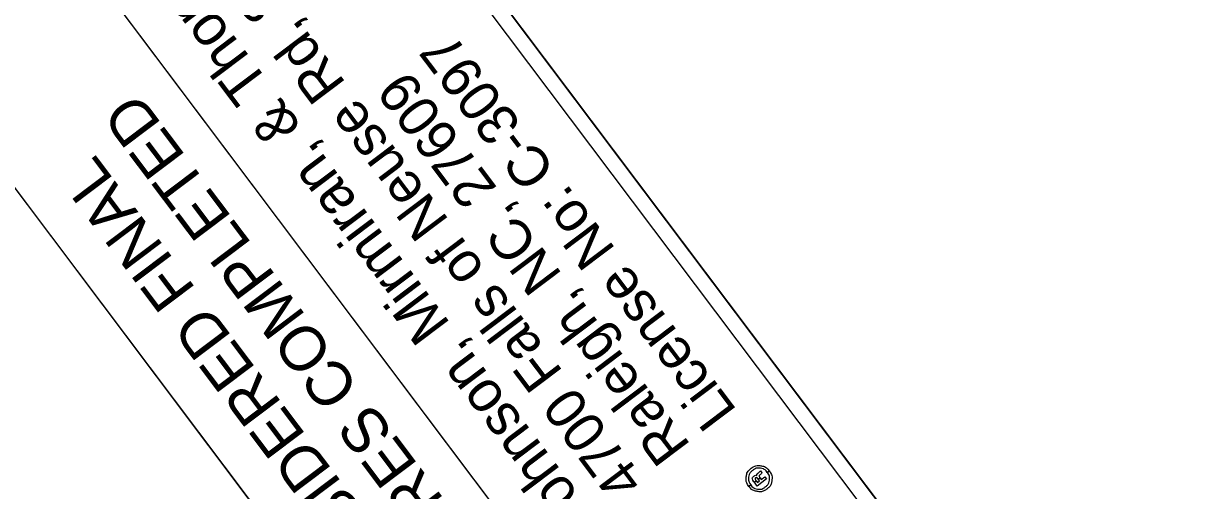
# Model space of a CAD drawing. Extents: x 1262749 to 1264921, y 774795 to 776798.
# Drawn here: x 1263207.9 to 1263352.6, y 776158.6 to 776215.8 of the extents above; entities that cross this region are included whole.
import ezdxf

# ---------------------------------------------------------------- set-up
doc = ezdxf.new("R2010")
doc.units = 0
for name, color, linetype in [('Default', 7, 'Continuous'), ('Sheet Border Standard 30in CELL', 7, 'Continuous'), ('Sheet Data Field CELL', 7, 'Continuous'), ('Sheet Layout Plan Border', 7, 'Continuous'), ('Sheet Plan Layout CELL', 7, 'Continuous')]:
    doc.layers.add(name, color=color, linetype=linetype)

msp = doc.modelspace()

# ---------------------------------------------------------------- linework, layer by layer
at = {"layer": 'Default'}
for p, q in [((1263200.09, 776243.7), (1263320.41, 776083.96)), ((1263301.64, 776069.83), (1263181.33, 776229.56))]:
    msp.add_line(p, q, dxfattribs=at)
at = {"layer": 'Sheet Border Standard 30in CELL'}
msp.add_lwpolyline([(1263151.63, 776082.06), (1263091.48, 776161.91), (1263181.32, 776229.57), (1263241.46, 776149.72)], close=True, dxfattribs=at)
at = {"layer": 'Sheet Data Field CELL'}
for p, q in [((1263298.46, 776159.92), (1263298.91, 776160.26)), ((1263298.91, 776160.26), (1263299.1, 776160)), ((1263299.2, 776160.8), (1263299.19, 776160.81)), ((1263299.2, 776160.8), (1263299.45, 776160.99)), ((1263299.45, 776160.99), (1263299.2, 776160.8)), ((1263299.44, 776161), (1263299.45, 776160.99)), ((1263296.93, 776159.09), (1263297.17, 776159.27)), ((1263297.17, 776159.27), (1263296.93, 776159.09)), ((1263297.61, 776159.6), (1263297.55, 776159.67)), ((1263297.61, 776159.6), (1263297.83, 776159.77)), ((1263297.83, 776159.77), (1263297.61, 776159.6)), ((1263297.96, 776159.14), (1263297.61, 776159.6)), ((1263297.8, 776159.8), (1263297.83, 776159.77)), ((1263297.83, 776159.77), (1263297.98, 776159.56)), ((1263299.1, 776160), (1263297.96, 776159.14)), ((1263297.98, 776159.56), (1263298.25, 776159.76)), ((1263298.1, 776159.97), (1263298.09, 776159.98)), ((1263298.1, 776159.97), (1263298.3, 776160.13)), ((1263298.3, 776160.13), (1263298.1, 776159.97)), ((1263298.25, 776159.76), (1263298.1, 776159.97)), ((1263298.3, 776160.14), (1263298.3, 776160.13)), ((1263298.3, 776160.13), (1263298.46, 776159.92))]:
    msp.add_line(p, q, dxfattribs=at)
msp.add_lwpolyline([(1263349.24, 776105.68), (1263228.9, 776265.45), (1263200.06, 776243.74), (1263320.41, 776083.96)], close=True, dxfattribs=at)
msp.add_lwpolyline([(1263298.1, 776160.76), (1263298.17, 776160.81), (1263298.2, 776160.85), (1263298.24, 776160.88), (1263298.34, 776161), (1263298.52, 776160.77)], dxfattribs=at)
for points, degree in [([(1263297.22, 776161.31), (1263297.57, 776161.58), (1263297.96, 776161.68), (1263298.39, 776161.63), (1263298.82, 776161.56), (1263299.17, 776161.35), (1263299.44, 776161)], 3), ([(1263296.93, 776159.09), (1263296.67, 776159.45), (1263296.56, 776159.84), (1263296.61, 776160.27), (1263296.66, 776160.69), (1263296.86, 776161.04), (1263297.22, 776161.31)], 3), ([(1263299.19, 776160.81), (1263298.98, 776161.09), (1263298.7, 776161.26), (1263298.36, 776161.31), (1263298.01, 776161.36), (1263297.68, 776161.27), (1263297.4, 776161.06), (1263297.12, 776160.85), (1263296.95, 776160.56), (1263296.9, 776160.21), (1263296.87, 776159.87), (1263296.95, 776159.56), (1263297.17, 776159.27)], 3), ([(1263299.45, 776160.99), (1263299.7, 776160.65), (1263299.81, 776160.25), (1263299.75, 776159.81), (1263299.7, 776159.38), (1263299.49, 776159.03), (1263299.14, 776158.77), (1263298.78, 776158.5), (1263298.39, 776158.4), (1263297.97, 776158.47), (1263297.54, 776158.54), (1263297.2, 776158.74), (1263296.93, 776159.09)], 3), ([(1263297.17, 776159.27), (1263297.38, 776158.99), (1263297.66, 776158.82), (1263297.99, 776158.77), (1263298.34, 776158.72), (1263298.67, 776158.8), (1263298.95, 776159.02), (1263299.23, 776159.23), (1263299.4, 776159.52), (1263299.45, 776159.87), (1263299.5, 776160.21), (1263299.41, 776160.52), (1263299.2, 776160.8)], 3), ([(1263297.55, 776159.67), (1263297.33, 776159.97), (1263297.34, 776160.2), (1263297.57, 776160.37), (1263297.67, 776160.45), (1263297.79, 776160.47), (1263297.92, 776160.42)], 3), ([(1263298.09, 776159.98), (1263297.96, 776160.15), (1263297.85, 776160.19), (1263297.75, 776160.12), (1263297.67, 776160.06), (1263297.68, 776159.95), (1263297.8, 776159.8)], 3), ([(1263297.92, 776160.42), (1263297.9, 776160.53), (1263297.97, 776160.64), (1263298.1, 776160.76)], 2), ([(1263298.52, 776160.77), (1263298.48, 776160.69), (1263298.44, 776160.62), (1263298.35, 776160.56), (1263298.25, 776160.48), (1263298.2, 776160.42), (1263298.19, 776160.37)], 3), ([(1263298.19, 776160.37), (1263298.19, 776160.32), (1263298.22, 776160.24), (1263298.3, 776160.14)], 2)]:
    msp.add_open_spline(points, degree=degree, dxfattribs=at)
at = {"layer": 'Sheet Layout Plan Border'}
msp.add_lwpolyline([(1264772.58, 775612.83), (1263930.27, 776731.11), (1263260.5, 776226.63), (1263374.36, 776075.45), (1263205.44, 775948.22), (1263933.87, 774981.11)], close=True, dxfattribs=at)
at = {"layer": 'Sheet Plan Layout CELL'}
for points in [[(1263963.99, 774941.16), (1264802.66, 775572.89), (1263900.2, 776771.04), (1263230.42, 776266.56), (1263374.36, 776075.45), (1263205.44, 775948.22)], [(1263374.36, 776075.45), (1263230.41, 776266.58), (1263061.46, 776139.36), (1263205.44, 775948.22)]]:
    msp.add_lwpolyline(points, close=True, dxfattribs=at)

# ---------------------------------------------------------------- texts
at = {"layer": 'Default'}
for s, p in [('UNLESS ALL SIGNATURES COMPLETED', (1263307.31, 776094.12)), ('DOCUMENT NOT CONSIDERED FINAL', (1263297.23, 776092.88))]:
    msp.add_text(s, height=5.4984, rotation=126.9874, dxfattribs=at).set_placement(p)
at = {"layer": 'Sheet Data Field CELL'}
for s, height, p in [('Johnson, Mirmiran, & Thompson Inc.', 5.1112, (1263278.23, 776155.32)), ('4700 Falls of Neuse Rd, Suite 100, ', 4.9652, (1263284.22, 776159.83)), ('License No: C-3097', 4.9652, (1263295.56, 776168.37)), ('Raleigh, NC, 27609', 4.9652, (1263289.89, 776164.1))]:
    msp.add_text(s, height=height, rotation=126.9874, dxfattribs=at).set_placement(p)

doc.saveas('drawing.dxf')
